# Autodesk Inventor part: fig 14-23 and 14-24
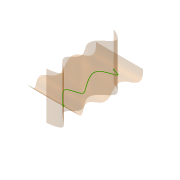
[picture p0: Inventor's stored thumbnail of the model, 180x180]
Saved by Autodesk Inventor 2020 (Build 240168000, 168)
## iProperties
Created: 2007-05
Part Number: fig 14-23 and 14-24
Document SubType Name: Modeling
Designer: Administrator
Density: 1 g/cm^3
Material: Generic
Appearance: Default
Author: Administrator
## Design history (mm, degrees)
node "Sketch1"
node "Sketch2"
sketch "Sketch3"
  geometry: 7 further points
  constraints: 7 other
extrude_surface "ExtrusionSrf1" sketch "Sketch3" dims "d0" = 50, "d1" = 0
sketch "Sketch4"
  geometry: 7 further points
  constraints: 7 other
extrude_surface "ExtrusionSrf2" sketch "Sketch4" dims "d2" = 50, "d3" = 0
sketch "3D Sketch1"
  node "3D Intersection1"
body "Srf1"
body "Srf2"
